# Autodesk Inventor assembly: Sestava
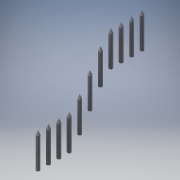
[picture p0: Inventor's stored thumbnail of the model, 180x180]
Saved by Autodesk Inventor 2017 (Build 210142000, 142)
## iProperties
Part Number: Sestava
Material: Všeobecné
Document SubType Name: Assembly
Designer: Polesny
Mass: 79.4414 g
Surface Area: 335.076 cm^2
Volume: 79.4414 cm^3
Density: 1 g/cm^3
Mass: 0,079
Author: Polesny
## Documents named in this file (3)
- C:\_2017_Soucasti\WorkSpace\Sestava.iam
- C:\_2017_Soucasti\WorkSpace\Skeleton.ipt
- C:\_2017_Soucasti\WorkSpace\Soucast.ipt
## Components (12 placed, 2 different names)
1. Skeleton:1 — Proti sobě:1
2. Soucast:1 — Proti sobě:1
3. Soucast:2
4. Soucast:3
5. Soucast:4
6. Soucast:5
7. Soucast:6
8. Soucast:7
9. Soucast:8
10. Soucast:9
11. Soucast:10
12. Soucast:11
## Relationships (1: Mate 1)
- Proti sobě:1 [Mate]: Skeleton:1 ↔ Soucast:1
